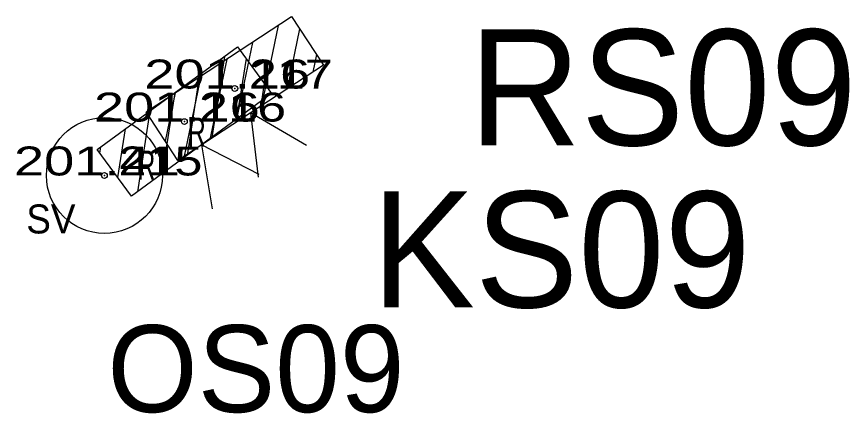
# Model space of a CAD drawing. Extents: x -466020 to -463400, y -1095586 to -1094005.
# Drawn here: x -465253.8 to -465239.43, y -1095453.9 to -1095447.06 of the extents above; entities that cross this region are included whole.
import ezdxf
from ezdxf.enums import TextEntityAlignment as Align

# ---------------------------------------------------------------- set-up
doc = ezdxf.new("R2010")
doc.units = 0
doc.header["$LTSCALE"] = 0.2
doc.header["$PDMODE"] = 32
doc.header["$PDSIZE"] = 0.1
for name, color, linetype in [('1', 7, 'Continuous'), ('2', 7, 'Continuous'), ('3', 7, 'Continuous'), ('4', 7, 'Continuous')]:
    doc.layers.add(name, color=color, linetype=linetype)
doc.layers.add('25', color=7, linetype='Continuous', lineweight=25)
doc.layers.add('33', color=7, linetype='Continuous', lineweight=25)

msp = doc.modelspace()

# ---------------------------------------------------------------- linework, layer by layer
at = {"layer": '1'}
for p in [(-465250.04, -1095448.3), (-465250.91, -1095448.87), (-465252.29, -1095449.8)]:
    msp.add_point(p, dxfattribs=at)
at = {"layer": '25'}
msp.add_circle((-465252.29, -1095449.8), 1, dxfattribs=at)
at = {"layer": '33'}
for p, q in [((-465249.293, -1095447.213), (-465249.581, -1095448.597)), ((-465248.921, -1095447.271), (-465249.137, -1095448.306)), ((-465249.736, -1095447.503), (-465250.024, -1095448.888)), ((-465250.22, -1095447.745), (-465250.436, -1095449.143)), ((-465248.631, -1095447.714), (-465248.694, -1095448.016)), ((-465250.179, -1095447.794), (-465250.468, -1095449.178)), ((-465249.846, -1095447.784), (-465250.008, -1095448.829)), ((-465250.648, -1095448.058), (-465250.864, -1095449.456)), ((-465250.624, -1095448.085), (-465250.912, -1095449.469)), ((-465249.533, -1095448.212), (-465249.58, -1095448.516)), ((-465251.075, -1095448.371), (-465251.292, -1095449.769)), ((-465251.067, -1095448.375), (-465251.24, -1095449.206)), ((-465251.504, -1095448.685), (-465251.72, -1095450.083)), ((-465251.51, -1095448.665), (-465251.53, -1095448.762)), ((-465251.932, -1095448.998), (-465252.061, -1095449.837)), ((-465252.359, -1095449.311), (-465252.374, -1095449.409))]:
    msp.add_line(p, q, dxfattribs=at)
for points in [[(-465248.511, -1095447.896), (-465251.021, -1095449.54), (-465251.569, -1095448.704), (-465249.059, -1095447.06)], [(-465248.511, -1095447.896), (-465251.021, -1095449.54), (-465251.569, -1095448.704), (-465249.059, -1095447.06)], [(-465249.404, -1095448.388), (-465251.825, -1095450.159), (-465252.416, -1095449.352), (-465249.995, -1095447.581)], [(-465249.404, -1095448.388), (-465251.825, -1095450.159), (-465252.416, -1095449.352), (-465249.995, -1095447.581)]]:
    msp.add_lwpolyline(points, close=True, dxfattribs=at)
for points in [[(-465248.8, -1095449.281), (-465249.766, -1095448.718), (-465249.636, -1095449.829)], [(-465249.621, -1095449.785), (-465250.615, -1095449.273), (-465250.428, -1095450.376)]]:
    msp.add_lwpolyline(points, dxfattribs=at)

# ---------------------------------------------------------------- texts
at = {"layer": '2'}
for s, width, p in [(' 217', 1.3, (-465250.04, -1095448.3)), (' 216', 1.35, (-465250.91, -1095448.87)), (' 215', 1.3, (-465252.29, -1095449.8))]:
    msp.add_text(s, height=0.5, dxfattribs=dict(at, width=width)).set_placement(p)
at = {"layer": '25'}
msp.add_text('OS09', height=1.5, dxfattribs=at).set_placement((-465249.675, -1095453.882), align=Align.CENTER)
at = {"layer": '3', "width": 1.4}
for s, p in [('201.16 ', (-465250.0395, -1095448.3)), ('201.16 ', (-465250.9095, -1095448.87)), ('201.41 ', (-465252.2895, -1095449.8))]:
    msp.add_text(s, height=0.5, dxfattribs=at).set_placement(p, align=Align.CENTER)
at = {"layer": '33'}
for s, p in [('RS09', (-465242.653, -1095449.28)), ('KS09', (-465244.408, -1095452.076))]:
    msp.add_text(s, height=2, dxfattribs=at).set_placement(p, align=Align.CENTER)
at = {"layer": '4'}
for s, width, p in [('R', 0.65, (-465250.54, -1095449.3)), ('R', 0.65, (-465251.41, -1095449.87)), ('SV', 0.95, (-465252.79, -1095450.8))]:
    msp.add_text(s, height=0.5, dxfattribs=dict(at, width=width)).set_placement(p, align=Align.RIGHT)

doc.saveas('drawing.dxf')
